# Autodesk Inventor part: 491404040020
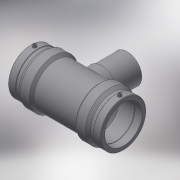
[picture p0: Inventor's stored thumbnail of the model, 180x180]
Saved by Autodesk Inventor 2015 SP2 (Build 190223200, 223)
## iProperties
Created: 2017-06
Part Number: 491404040020
Material: Generic
Description: PLASSON REDUCING TEE 40x20x40
Document SubType Name: Modeling
Designer: KIM
Mass: 147.193 g
Surface Area: 460.471 cm^2
Volume: 147.193 cm^3
Density: 1 g/cm^3
Appearance: Default
Author: KIM
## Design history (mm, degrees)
derived "491404.ipt"
feature "Solid1::491404.ipt"
tag "TaggingFeature1"
body "Solid1"
other parameters: "d2" = 56, "d3" = 43, "d4" = 24, "d5" = 50.4, "d6" = 38, "d8" = 168 deg, "d10" = 17.2, "d11" = 5.73333, "d14" = 17.6296, "d17" = 36, "d19" = 3.52592, "d20" = 168 deg, "d22" = 52.08, "d23" = 56, "d25" = 135 deg, "d26" = 84, "d29" = 47, "d30" = 15, "d31" = 48, "d34" = 5 deg, "d35" = 15, "d39" = 5 deg, "d41" = 4, "d42" = 14, "d43" = 0, "d45" = 4, "d46" = 6, "d47" = 0, "d48" = -72, "d51" = 0, "d52" = 16, "d54" = 0, "d55" = 50.4, "d56" = 56, "d57" = 42, "d58" = 135 deg, "d59" = 43, "d60" = 43, "d61" = 135 deg, "d62" = 72, "d72" = 54.6, "d73" = 27.3, "d74" = -72, "d75" = 21, "d77" = 0, "d78" = 16, "d80" = 0, "d82" = 44, "d83" = 0, "d84" = 3, "d85" = 0, "d86" = 14.33333, "d87" = 51.0384, "d88" = 5.73333, "d89" = 3, "d90" = 0, "L_1" = 43, "D_" = 56, "A_" = 47, "d_2" = 12, "H_" = 72
